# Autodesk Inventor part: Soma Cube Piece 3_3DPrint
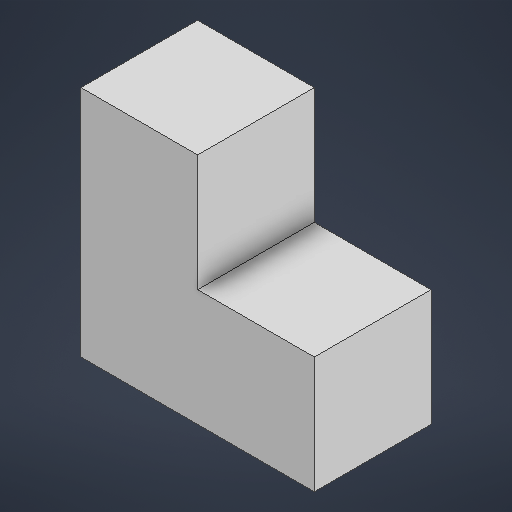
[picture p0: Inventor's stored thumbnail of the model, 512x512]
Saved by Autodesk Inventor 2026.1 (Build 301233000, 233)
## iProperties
Created: 2025-12
Part Number: Soma Cube Piece 3_3DPrint
Material: Generic
Document SubType Name: Modeling
Designer: egberbos000
Density: 1 g/cm^3
Appearance: Default
Author: egberbos000
Part Number: Soma Cube Piece 3
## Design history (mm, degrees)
sketch "Sketch1"
  geometry: L1 (0, 0)-(25.4, 0); L2 (25.4, 0)-(25.4, 25.4); L3 (25.4, 25.4)-(0, 25.4); L4 (0, 25.4)-(0, 0); L5 (25.4, 25.4)-(0, 25.4); L6 (0, 25.4)-(0, 50.8); L7 (0, 50.8)-(25.4, 50.8); L8 (25.4, 50.8)-(25.4, 25.4); L9 (25.4, 25.4)-(50.8, 25.4); L10 (50.8, 25.4)-(50.8, 0); L11 (50.8, 0)-(25.4, 0); L12 (25.4, 0)-(25.4, 25.4); 2 further points
  constraints: 24 end point, 6 parallel, 3 horizontal, 3 perpendicular
  dimensions: "d0" = 25.4 distance of L2.end L3.end; "d1" = 25.4 distance of L1.end L2.end (= d0); "d2" = 25.4 distance of L6.end L7.end (= d0); "d3" = 25.4 distance of L7.end L2.end (= d0); "d4" = 25.4 distance of L2.end L9.end (= d0); "d5" = 25.4 distance of L9.end L10.end (= d0)
extrude "Extrusion1" new body sketch "Sketch1" distance "d6" = 25.4; taper "d7" = 0 deg
body "Solid1"
